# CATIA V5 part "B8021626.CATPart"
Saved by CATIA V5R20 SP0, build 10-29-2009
Part number: B8021626
Revision: 9
Definition: design
Nomenclature: B8021626
Source: made
Description: NOT SPECIFIED
Bounding box of the stored display mesh (mm): x -16 to 16, y -16 to 16, z -9 to 26
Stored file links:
  C:\Users\Utente\Desktop\3D files B802\B8021626.CATPart
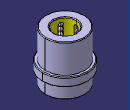
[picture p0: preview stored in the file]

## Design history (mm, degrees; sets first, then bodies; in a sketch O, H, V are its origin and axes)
Body1 "MANIFOLD_SOLID_BREP #38" (main body)
  Solid1: solid without history
Body2 "MANIFOLD_SOLID_BREP #76"
  Solid2: solid without history
Body3 "MANIFOLD_SOLID_BREP #114"
  Solid3: solid without history
Body4 "MANIFOLD_SOLID_BREP #152"
  Solid4: solid without history
Body5 "MANIFOLD_SOLID_BREP #190"
  Solid5: solid without history
Body6 "MANIFOLD_SOLID_BREP #228"
  Solid6: solid without history
Body7 "MANIFOLD_SOLID_BREP #266"
  Solid7: solid without history
Body8 "MANIFOLD_SOLID_BREP #304"
  Solid8: solid without history
Body9 "MANIFOLD_SOLID_BREP #2006"
  Solid9: solid without history
Body10 "MANIFOLD_SOLID_BREP #2044"
  Solid10: solid without history
Body11 "MANIFOLD_SOLID_BREP #2082"
  Solid11: solid without history
Body12 "MANIFOLD_SOLID_BREP #2120"
  Solid12: solid without history
Body13 "MANIFOLD_SOLID_BREP #2158"
  Solid13: solid without history
Body14 "MANIFOLD_SOLID_BREP #2196"
  Solid14: solid without history
Body15 "MANIFOLD_SOLID_BREP #2234"
  Solid15: solid without history
Body16 "MANIFOLD_SOLID_BREP #2272"
  Solid16: solid without history
Body17 "MANIFOLD_SOLID_BREP #2310"
  Solid17: solid without history
Body18 "MANIFOLD_SOLID_BREP #2348"
  Solid18: solid without history
Body19 "MANIFOLD_SOLID_BREP #2386"
  Solid19: solid without history
Body20 "MANIFOLD_SOLID_BREP #2424"
  Solid20: solid without history
Body21 "MANIFOLD_SOLID_BREP #2462"
  Solid21: solid without history
Body22 "MANIFOLD_SOLID_BREP #2500"
  Solid22: solid without history
Body23 "MANIFOLD_SOLID_BREP #2538"
  Solid23: solid without history
Body24 "MANIFOLD_SOLID_BREP #2576"
  Solid24: solid without history
Body25 "MANIFOLD_SOLID_BREP #2614"
  Solid25: solid without history
Body26 "MANIFOLD_SOLID_BREP #2652"
  Solid26: solid without history
Body27 "MANIFOLD_SOLID_BREP #2690"
  Solid27: solid without history
Body28 "MANIFOLD_SOLID_BREP #2728"
  Solid28: solid without history
Body29 "MANIFOLD_SOLID_BREP #2766"
  Solid29: solid without history
Body30 "MANIFOLD_SOLID_BREP #2804"
  Solid30: solid without history
Body31 "MANIFOLD_SOLID_BREP #2842"
  Solid31: solid without history
Body32 "MANIFOLD_SOLID_BREP #2880"
  Solid32: solid without history
Body33 "MANIFOLD_SOLID_BREP #2918"
  Solid33: solid without history
Body34 "MANIFOLD_SOLID_BREP #2956"
  Solid34: solid without history
Body35 "MANIFOLD_SOLID_BREP #2994"
  Solid35: solid without history
Body36 "MANIFOLD_SOLID_BREP #3032"
  Solid36: solid without history
Body37 "MANIFOLD_SOLID_BREP #3070"
  Solid37: solid without history
Body38 "MANIFOLD_SOLID_BREP #3108"
  Solid38: solid without history
Body39 "MANIFOLD_SOLID_BREP #3146"
  Solid39: solid without history
Body40 "MANIFOLD_SOLID_BREP #3184"
  Solid40: solid without history
Body41 "MANIFOLD_SOLID_BREP #3222"
  Solid41: solid without history
Body42 "MANIFOLD_SOLID_BREP #3260"
  Solid42: solid without history
Body43 "MANIFOLD_SOLID_BREP #3298"
  Solid43: solid without history
Body44 "MANIFOLD_SOLID_BREP #3336"
  Solid44: solid without history
Body45 "MANIFOLD_SOLID_BREP #3374"
  Solid45: solid without history
Body46 "MANIFOLD_SOLID_BREP #3412"
  Solid46: solid without history
Body47 "MANIFOLD_SOLID_BREP #3450"
  Solid47: solid without history
Body48 "MANIFOLD_SOLID_BREP #3488"
  Solid48: solid without history
Body49 "MANIFOLD_SOLID_BREP #3526"
  Solid49: solid without history
Body50 "MANIFOLD_SOLID_BREP #3564"
  Solid50: solid without history
Body51 "MANIFOLD_SOLID_BREP #3602"
  Solid51: solid without history
Body52 "MANIFOLD_SOLID_BREP #3640"
  Solid52: solid without history
Body53 "MANIFOLD_SOLID_BREP #3678"
  Solid53: solid without history
Body54 "MANIFOLD_SOLID_BREP #3716"
  Solid54: solid without history
Body55 "MANIFOLD_SOLID_BREP #3754"
  Solid55: solid without history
